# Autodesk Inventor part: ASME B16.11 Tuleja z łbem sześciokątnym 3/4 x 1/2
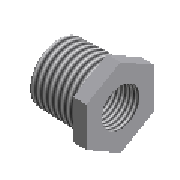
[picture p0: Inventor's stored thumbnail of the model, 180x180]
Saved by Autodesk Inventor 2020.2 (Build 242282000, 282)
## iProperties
Manager: www.cadconsulting.pl
Company: Fabian Stasiak CAD Consulting
Created: 2014-02
Part Number: ASME B16.11 Tuleja z łbem sześciokątnym 3/4 x 1/2
Material: Stal
Description: Tuleja z łbem sześciokątnym
Document SubType Name: Modeling
Standard: ASME B16.11
Designer: F.Stasiak
Standard Revision: 2005
Standards Organization: ANSI
Language: pl-PL
Size Designation: 3/4 x 1/2
Categories: <MemberInstance><Categories><Category DisplayName="Rury cienko- i grubościenne" InternalName="4347fa0f-2144-441d-94cd-e3e15c92b736" Mnemonic="TUBEANDPIPE"><Cate
Density: 1 g/cm^3
Appearance: Płyta
Catalog Web Link: www.expertbooks.pl
NAME: PIPING: ASME B16.11 Hex Head Bushing
DATA: <meta><inlinegroups number="1" deflen="1.4224"></inlinegroups><connections number="2"></connections><angles><a>3.14159265358979</a></angles></meta>
IsCustomPart: 0
Author: F.Stasiak
Subject: Zbiór ćwiczeń. Autodesk Inventor 2020. Kurs Professional
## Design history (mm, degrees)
sketch "Sketch1"
  geometry: L1 (0, 0)-(-21.336, 0); L2 (-21.336, 0)-(-21.336, 9.16); L3 (-21.336, 13.462)-(-15.748, 13.462); L4 (-15.748, 13.462)-(-15.748, 13.473); L5 (-15.748, 13.473)-(-14.635, 13.473); L6 (-14.635, 13.473)-(0, 13.015); L7 (0, 13.015)-(0, 8.494); L8 (0, 8.494)-(-21.336, 9.16); L9 (0, 8.494)-(0, 0); L10 (-21.336, 13.462)-(-21.336, 9.16); L11 (-14.635, 13.473)-(-14.635, 0); L12 (-8.611, 13.284)-(-8.611, 0)
  constraints: 24 end point, 5 parallel, 5 perpendicular, 3 point on line, 1 horizontal
  dimensions: "d0" = 1.78991 deg angle of L1 L8; "d1" = 18.32077 diameter of L2.end L1 (= MD); "d2" = 1.11298 distance of L4.end L5.end (= L); "d3" = 15.748 distance between parallel lines of L9 L4 (= A); "d4" = 5.588 distance between parallel lines of L4 L10 (= G); "d5" = 26.924 diameter of L3 L1 (= F1); "d9" = 8.6106 distance between parallel lines of L9 L12 (= Lh); "d10" = 26.56865 diameter of L12.start L1 (= Dh)
revolve "Revolve1" sketch "Sketch1" stored, may be unused: angle "d8" = 90 deg
sketch "Sketch2"
  geometry: L1 (-13.462, 7.772)-(0, 15.545); L2 (0, 15.545)-(13.462, 7.772); L3 (13.462, 7.772)-(13.462, -7.772); L4 (13.462, -7.772)-(0, -15.545); L5 (0, -15.545)-(-13.462, -7.772); L6 (-13.462, -7.772)-(-13.462, 7.772); 4 further points
  constraints: 12 end point, 1 coincident, 1 horizontal alignment, 1 midpoint, 1 vertical, 12 other
extrude "Extrude1" join sketch "Sketch2" distance "d6" = 5.588 (= G); taper "d7" = 0 deg
workpoint "Work Point1"
workaxis "Work Axis1"
workpoint "Work Point2"
workaxis "Work Axis2"
workpoint "Work Point3"
workpoint "Work Point4"
body "Solid1"
feature "Gwint1" dims "d11" = 25.4, "d12" = 0
feature "Gwint2" dims "d13" = 25.4, "d14" = 0
other parameters: "MD" = 18.32077 [user parameter; used in 1 equation term], "A" = 15.748 [user parameter; used in 1 equation term], "G" = 5.588 [user parameter; used in 2 equation terms], "F1" = 26.924 [user parameter; used in 1 equation term], "p" = 1.8143 [user parameter], "L" = 1.11298 [user parameter; used in 1 equation term], "Dh" = 26.56865 [user parameter; used in 1 equation term], "Lh" = 8.6106 [user parameter; used in 1 equation term], "Size_Designation" = 12.345 [user parameter]
